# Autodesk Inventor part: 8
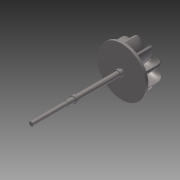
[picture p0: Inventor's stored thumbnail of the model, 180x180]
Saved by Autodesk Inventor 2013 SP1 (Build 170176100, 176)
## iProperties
Created: 2013-05
Part Number: 8
Material: Generic
Document SubType Name: Modeling
Designer: 50384
Density: 1 g/cm^3
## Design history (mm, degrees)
node "exhaustwheel1"
node "exhaustwheel"
node "Base1"
